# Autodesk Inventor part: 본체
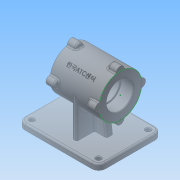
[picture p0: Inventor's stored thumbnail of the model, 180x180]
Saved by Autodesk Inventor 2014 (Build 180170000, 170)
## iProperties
Created: 2015-12
Part Number: 본체
Material: 일반
Document SubType Name: Modeling
Designer: net
Density: 1 g/cm^3
Appearance: 기본값
Author: net
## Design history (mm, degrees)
sketch "스케치1"
  geometry: L1 (-58, 55)-(58, 55); L2 (70, 43)-(70, -43); L3 (58, -55)-(-58, -55); L4 (-70, -43)-(-70, 43); C1 r 4 at (-58, 43); C2 r 4 at (-58, -43); C3 r 4 at (58, -43); C4 r 4 at (58, 43); A1 r 12 centre (-58, 43) between (-58, 55) and (-70, 43); A2 r 12 centre (-58, -43) between (-70, -43) and (-58, -55); A3 r 12 centre (58, -43) between (58, -55) and (70, -43); A4 r 12 centre (58, 43) between (70, 43) and (58, 55); 3 further points
  constraints: 8 centre point, 8 end point, 8 point on circle, 8 tangent, 4 coincident, 3 equal radius, 2 midpoint, 2 parallel, 1 horizontal, 1 horizontal alignment, 1 perpendicular, 1 vertical alignment
  dimensions: "d0" = 140 distance between parallel lines of L2 L4; "d1" = 110 distance between parallel lines of L3 L1; "d2" = 12 radius of A1; "d3" = 12 radius of A2; "d4" = 12 radius of A3; "d5" = 12 radius of A4; "d6" = 8 diameter of C1
extrude "돌출1" new body sketch "스케치1" distance "d7" = 10; taper "d8" = 0 deg
sketch "스케치2"
  geometry: L1 (-70, 43)-(-70, -43) reference; L2 (58, 55)-(-58, 55) reference; L3 (6, 37)-(14, 37); L4 (14, 37)-(14, -37); L5 (14, -37)-(6, -37); L6 (6, -37)-(6, 37); L7 (-15, 6)-(35, 6); L8 (35, 6)-(35, -6); L9 (35, -6)-(-15, -6); L10 (-15, -6)-(-15, 6); L11 (10, 37)-(10, -37); 1 further point
  constraints: 18 end point, 4 parallel, 2 horizontal, 2 midpoint, 2 perpendicular
  dimensions: "d9" = 8 distance between parallel lines of L4 L6; "d10" = 12 distance between parallel lines of L9 L7; "d11" = 49 distance between parallel lines of L7 L2; "d12" = 76 distance between parallel lines of L6 L1; "d13" = 50 distance between parallel lines of L8 L10; "d14" = 74 distance between parallel lines of L5 L3; "d15" = 8 distance of L3.start L3.end (derived); "d16" = 37 distance from line of point (0, 0) L3 (= 0.5 x d14); "d17" = 80 distance between parallel lines of L11 L1 (derived); "d18" = 6 distance from line of point (0, 0) L7 (derived); "d19" = 25 distance between parallel lines of L11 L10
extrude "돌출2" join sketch "스케치2" distance "d20" = 70; taper "d21" = 0 deg
sketch "스케치3"
  geometry: L1 (32.5, 80)-(-52.5, 80); L2 (32.5, 80)-(32.5, 117); L3 (32.5, 117)-(-52.5, 117); L4 (-52.5, 117)-(-52.5, 80); L5 (58, 0)-(-58, 0) reference; L6 (70, 0)-(70, 10) reference; L7 (32.5, 101)-(-52.5, 101); 1 further point
  constraints: 10 end point, 4 perpendicular, 2 point on line, 1 horizontal
  dimensions: "d22" = 85 distance of L2.end L3.end; "d23" = 80 distance between parallel lines of L5 L1; "d24" = 74 diameter of L3 L1; "d25" = 37.5 distance between parallel lines of L2 L6; "d26" = 42 diameter of L7 L1
revolve "회전1" sketch "스케치3" stored, may be unused: angle "d27" = 90 deg
sketch "스케치4"
  geometry: L1 (32.5, 43)-(32.5, 117) reference; L2 (-52.5, 43)-(-52.5, 117) reference; L3 (-14, 80)-(-14, 80) reference; L4 (-6, 80)-(-6, 80) reference; L5 (-58, 0)-(58, 0) reference; L6 (58, 0)-(58, 10) reference; L7 (-58, 10)-(58, 10) reference; L8 (-58, 0)-(-58, 10) reference; L9 (-30.948, 43)-(-35, 10); L10 (-52.5, 43)-(32.5, 43) reference; L11 (-10, 117)-(-10, 0); L12 (-14, 80)-(-6, 80) reference; L13 (-6, 80)-(-14, 80) reference; 1 further point
  constraints: 4 end point, 3 point on line, 1 perpendicular
  dimensions: "d28" = 97 deg angle of L7 L9; "d30" = 42.5 distance between parallel lines of L11 L2; "d31" = 25 distance from line of L11 L9.end
feature "리브1" sketch "스케치4" dims "d36" = 1, "d37" = 12, "d38" = 0, "d39" = 0, "d40" = 1, "d41" = 1
node "작업 평면1"
sketch "스케치5"
  geometry: C1 r 37 at (0, 0) reference; 1 further point
sketch "스케치11"
  geometry: C1 r 7 at (-37, 0); 3 further points
  constraints: 3 horizontal alignment, 1 centre point, 2 other
  dimensions: "d71" = 14 diameter of C1
extrude "돌출5" join sketch "스케치11" distance "d72" = 15; taper "d73" = 0 deg
hole "구멍1" diameter "d76" = 3.242; stored, may be unused: countersink angle "d80" = 90 deg, drill point angle "d82" = 118 deg; dims "d74" = 10, "d75" = 10, "d77" = 9, "d78" = 4, "d79" = 2, "d81" = 11
hole "구멍2" diameter "d88" = 42; stored, may be unused: countersink angle "d92" = 90 deg, drill point angle "d94" = 0 deg; dims "d86" = 10, "d87" = 10, "d89" = 9, "d90" = 47, "d91" = 22, "d93" = 11
hole "구멍3" diameter "d97" = 42; stored, may be unused: countersink angle "d101" = 90 deg, drill point angle "d103" = 0 deg; dims "d95" = 10, "d96" = 10, "d98" = 9, "d99" = 47, "d100" = 22, "d102" = 11
chamfer "모따기1" distance "d104" = 1; stored, may be unused: second distance "d105" = 2, angle "d106" = 20 deg
fillet "모깎기1" dims "d107" = 0.3
sketch "스케치12"
  geometry: L1 (0, 0)-(-26.163, -26.163); L2 (0, 0)-(-36.338, 0); C1 r 21 at (0, 0) reference; A1 r 37 centre (0, 0) between (-36.338, -6.969) and (-6.969, -36.338) reference; 2 further points
  constraints: 4 end point, 1 coincident, 1 horizontal, 1 horizontal alignment, 1 point on circle
  dimensions: "d108" = 45 deg angle of L2 L1 (derived); "d109" = 37 distance of L1.start L1.end (derived); "d110" = 25.69473 distance from line of L2.end L1
node "작업 평면2"
sketch "스케치13"
  geometry: L1 (42.5, 37)-(-42.5, 37) reference; L2 (-68, -95.459)-(48, -95.459) reference; L3 (48, -95.459)-(48, -88.388) reference; L4 (-68, -88.388)-(48, -88.388) reference; L5 (-68, -95.459)-(-68, -88.388) reference; L6 (4, -75.66)-(-4, -75.66) reference; L7 (4, -75.66)-(4, -26.163) reference; L8 (-4, -26.163)-(4, -26.163) reference; L9 (-4, -75.66)-(-4, -26.163) reference; L10 (-42.5, 20.767)-(-42.5, -20.767) reference; 3 further points
  constraints: 1 midpoint, 1 vertical alignment, 1 other
  dimensions: "d111" = 42.5 distance from line of point (0, 1.283) L10 (derived); "d112" = 76.94384 distance from line of point (0, 1.283) L6
feature "엠보싱1" sketch "스케치13" dims "d0" = 140, "d1" = 110, "d2" = 12, "d3" = 12, "d4" = 12, "d5" = 12, "d6" = 8, "d113" = 0.5, "d114" = 0
fillet "모깎기2" dims "d115" = 3
fillet "모깎기3" dims "d116" = 3
fillet "모깎기4" dims "d117" = 3
fillet "모깎기5" dims "d118" = 3
fillet "모깎기6" dims "d119" = 3
chamfer "모따기2" distance "d120" = 1; stored, may be unused: second distance "d121" = 2, angle "d122" = 20 deg
sketch "스케치10"
  geometry: L1 (-52.5, 43)-(-52.5, 117) reference; L2 (-52.5, 117)-(32.5, 117) reference; L3 (-52.5, 117)-(-52.5, 124); L4 (-52.5, 124)-(-42.148, 124); L5 (-39.329, 122.026)-(-38.218, 118.974); L6 (-37.5, 117)-(-52.5, 117); L7 (-52.5, 117)-(-35.399, 117); A1 r 3 centre (-42.148, 121) between (-39.329, 122.026) and (-42.148, 124); A2 r 3 centre (-35.399, 120) between (-38.218, 118.974) and (-35.399, 117); 1 further point
  constraints: 10 end point, 5 tangent, 4 point on circle, 2 centre point, 2 collinear, 2 perpendicular, 2 point on line
  dimensions: "d65" = 15 distance from line of L6.start L3; "d66" = 110 deg angle of L2 L5; "d67" = 7 distance between parallel lines of L2 L4; "d68" = 3 radius of A1; "d69" = 6 diameter of A2; "d70" = 65.77848 distance from line of L2.end L5
sketch "스케치9"
  geometry: L1 (-52.5, 43)-(-52.5, 117) reference; L2 (-40.048, 124)-(-52.5, 124); L3 (-52.5, 124)-(-52.5, 117); L4 (-40.048, 124)-(-37.5, 117); L5 (-52.5, 117)-(32.5, 117) reference; L6 (-52.5, 117)-(-37.5, 117); L7 (-52.5, 124)-(-52.5, 117); 1 further point
  constraints: 10 end point, 3 point on line, 1 collinear
revolve "회전2" sketch "스케치9" stored, may be unused: angle "d64" = 90 deg
sketch "스케치6"
  geometry: C1 r 7 at (0, 37); 2 further points
  constraints: 2 vertical alignment, 1 centre point, 1 other
  dimensions: "d42" = 14 diameter of C1
extrude "돌출3" join sketch "스케치6" distance "d43" = 15; taper "d44" = 0 deg
sketch "스케치7"
  geometry: L1 (-52.5, 86.969)-(-37.5, 86.969) reference; L2 (-37.5, 86.969)-(-37.5, 73.031) reference; L3 (-37.5, 73.031)-(-52.5, 73.031) reference; L4 (-52.5, 73.031)-(-52.5, 86.969) reference; L5 (32.5, 43)-(32.5, 117) reference; L6 (-30.921, 43.217)-(-14, 43.217) reference; L7 (-14, 80)-(-14, 43.217) reference; L8 (-14, 80)-(-6, 80) reference; L9 (-6, 43.217)-(-6, 80) reference; L10 (-6, 43.217)-(10.921, 43.217) reference; L11 (10.921, 43.217)-(10.921, 43.217) reference; L12 (10.921, 43.217)-(-6, 43.217) reference; L13 (-6, 80)-(-6, 43.217) reference; L14 (-6, 80)-(-14, 80) reference; L15 (-14, 43.217)-(-14, 80) reference; L16 (-14, 43.217)-(-30.921, 43.217) reference; L17 (-30.921, 43.217)-(-30.921, 43.217) reference; L18 (-52.5, 117)-(-52.5, 121); L19 (-52.5, 121)-(-38.956, 121); L20 (-38.956, 121)-(-37.5, 117); L21 (-37.5, 117)-(-52.5, 117); L22 (-52.5, 117)-(32.5, 117) reference; L23 (-52.5, 43)-(-52.5, 117) reference; L24 (-52.5, 117)-(-52.5, 113.454); L25 (-52.5, 117)-(-52.5, 111.906); L26 (-34.978, 110.071)-(-37.5, 117); L27 (-52.5, 117)-(-52.5, 110.071); L28 (-52.5, 110.071)-(-34.978, 110.071); L29 (-52.5, 121)-(-52.5, 110.071); 1 further point
  constraints: 20 end point, 4 perpendicular, 3 collinear, 3 point on line, 1 parallel
  dimensions: "d45" = 15 distance from line of L20.end L18; "d46" = 110 deg angle of L22 L20; "d47" = 4 distance between parallel lines of L21 L19; "d48" = 66.85366 distance between parallel lines of L6 L28; "d49" = 54.38901 distance from line of L24.end L11; "d50" = 54.57765 distance from line of L25.end L11
extrude "돌출4" join sketch "스케치7" stored distance "d51" = 8; taper "d52" = 0 deg
sketch "스케치8"
  geometry: L1 (-41, -33)-(-36.783, -33) reference; L2 (-41, -41)-(-41, -33) reference; L3 (-36.783, -41)-(-41, -41) reference; A1 r 37 centre (0, -37) between (-36.783, -41) and (6.969, -0.662) reference; A2 r 7 centre (0, 0) between (6.969, -0.662) and (-6.969, -0.662) reference; A3 r 37 centre (0, -37) between (-6.969, -0.662) and (-36.783, -33) reference; 1 further point
node "솔리드1"
mirror "대칭1"
pattern_circular "원형 패턴1" dims angle "d84" = 360 deg
mirror "대칭2"
node "투영된 루프1"
node "투영된 루프2"
node "투영된 루프3"
node "투영된 루프4"
node "투영된 루프5"
